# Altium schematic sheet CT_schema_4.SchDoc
size 517 x 390 mm
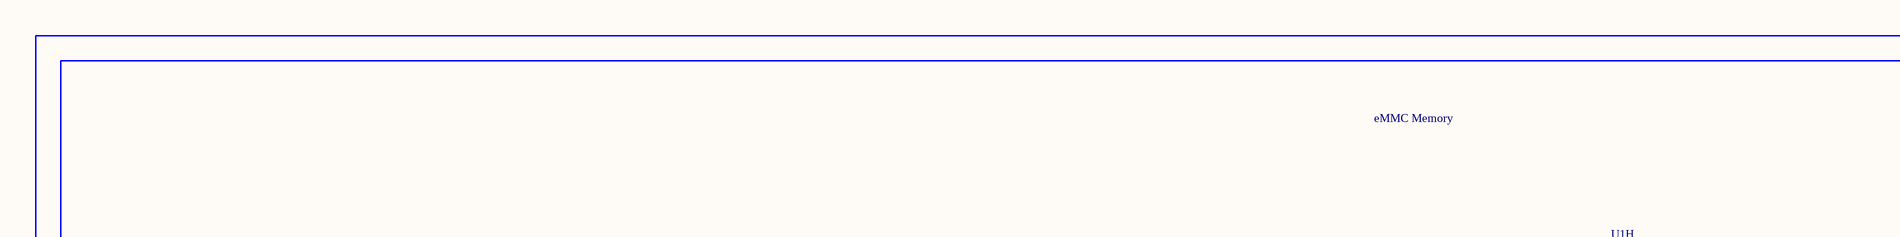
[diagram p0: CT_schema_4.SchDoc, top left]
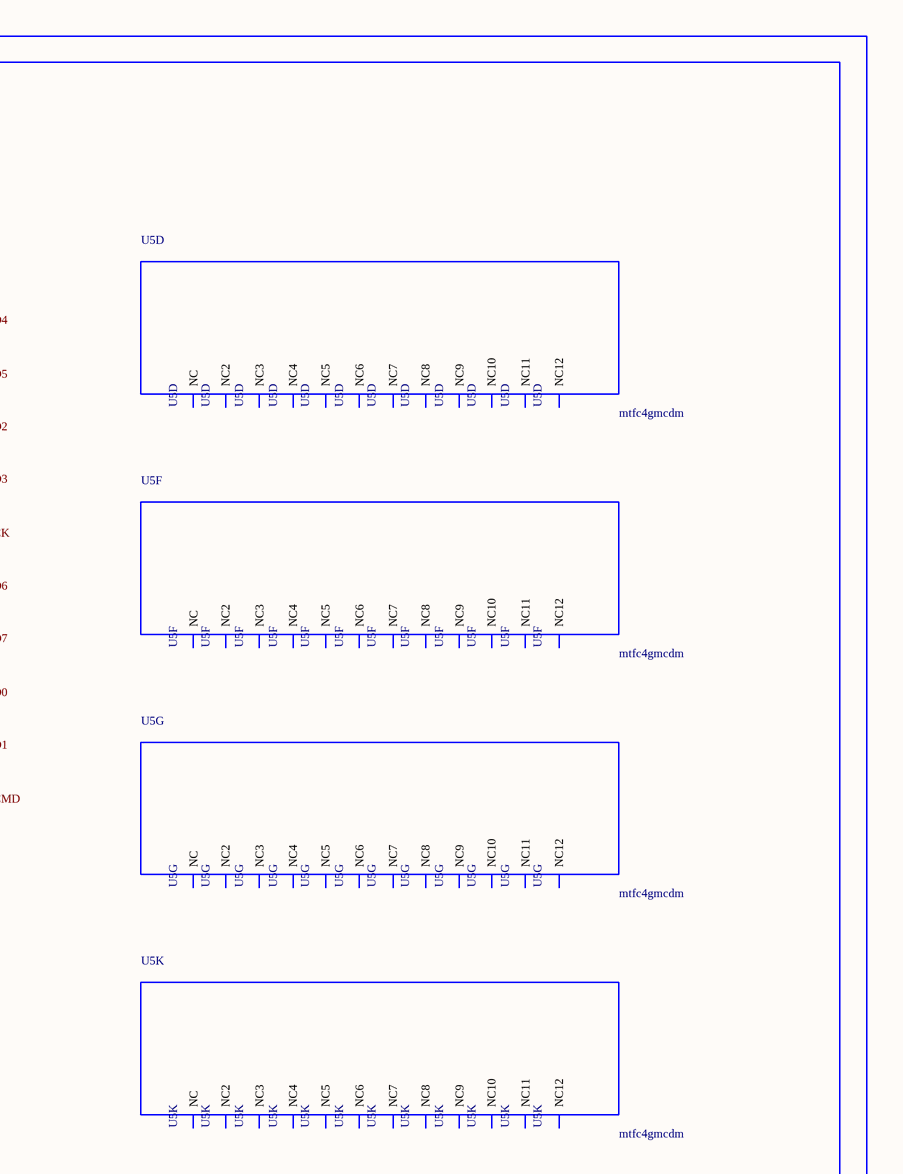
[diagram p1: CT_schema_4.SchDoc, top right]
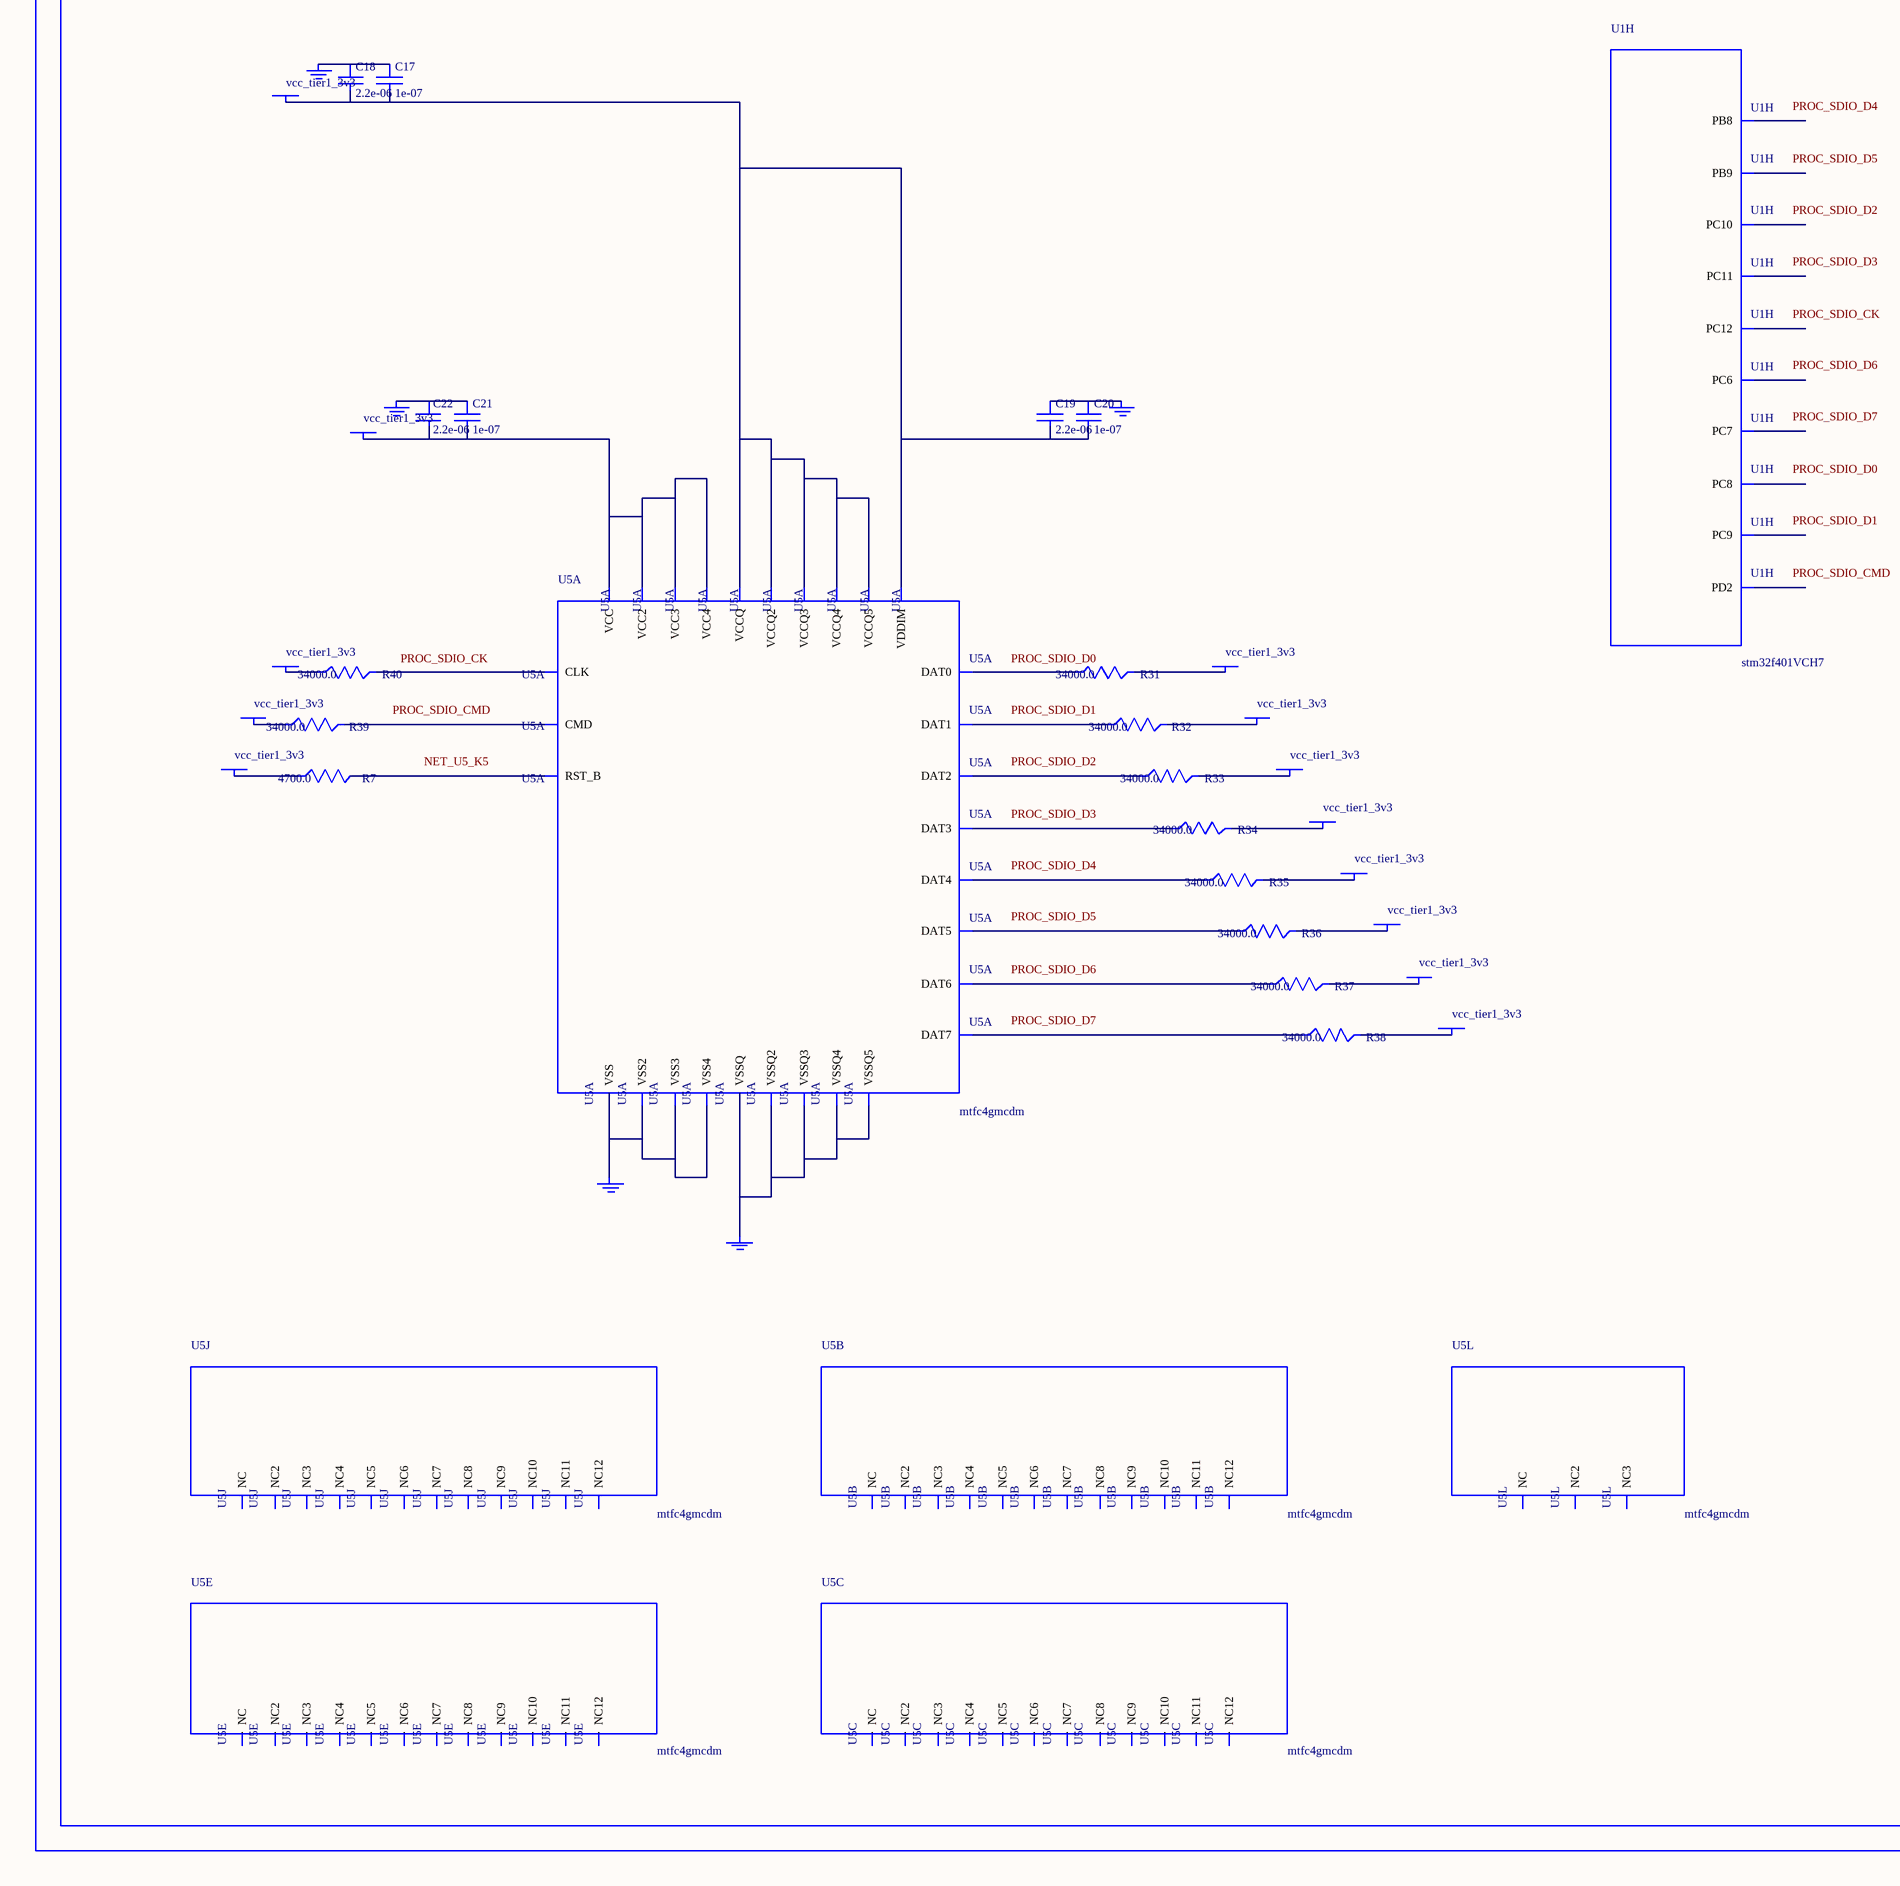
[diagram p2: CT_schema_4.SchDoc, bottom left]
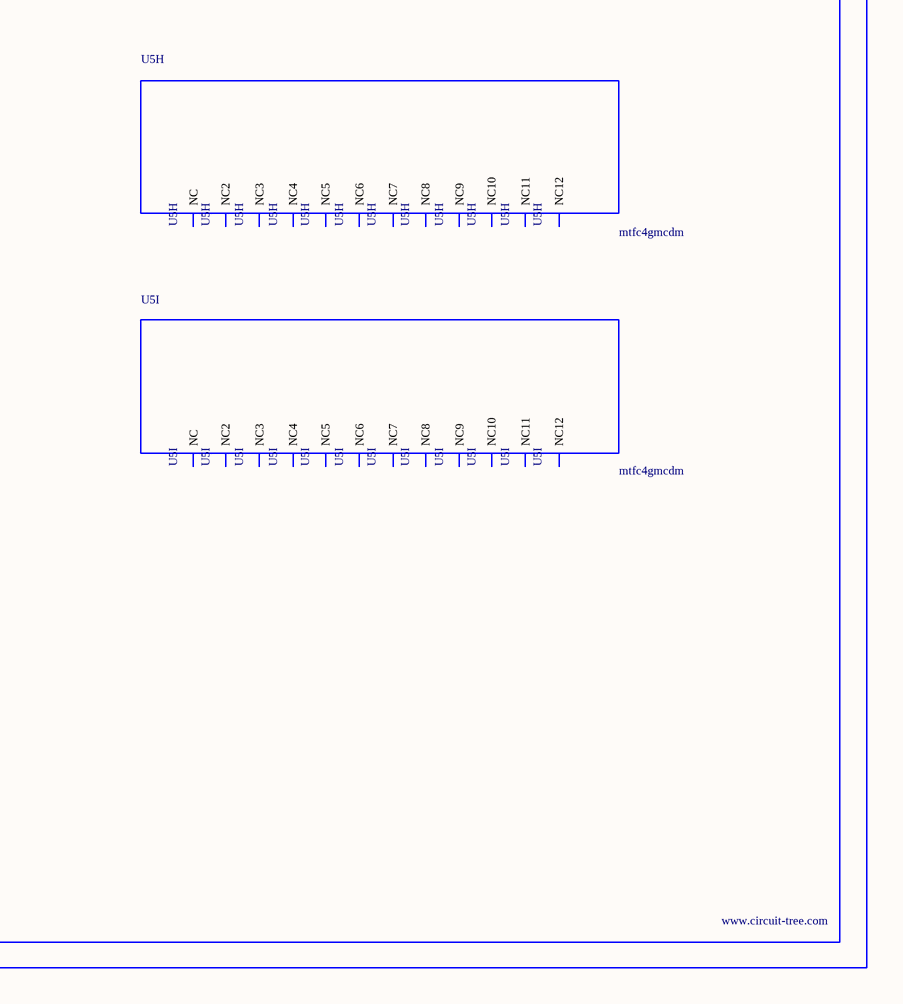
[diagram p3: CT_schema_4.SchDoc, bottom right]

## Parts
BORDER3  (no value)
C17  1e-07  [C0402]
C18  2.2e-06  [C0603]
C19  2.2e-06  [C0603]
C20  1e-07  [C0402]
C21  1e-07  [C0402]
C22  2.2e-06  [C0603]
GND_INSTANCE_3_0  (no value)
GND_INSTANCE_3_1  (no value)
GND_INSTANCE_3_2  (no value)
GND_INSTANCE_3_3  (no value)
GND_INSTANCE_3_4  (no value)
POWER_INSTANCE_3_0  vcc_tier1_3v3
POWER_INSTANCE_3_1  vcc_tier1_3v3
POWER_INSTANCE_3_2  vcc_tier1_3v3
POWER_INSTANCE_3_3  vcc_tier1_3v3
POWER_INSTANCE_3_4  vcc_tier1_3v3
POWER_INSTANCE_3_5  vcc_tier1_3v3
POWER_INSTANCE_3_6  vcc_tier1_3v3
POWER_INSTANCE_3_7  vcc_tier1_3v3
POWER_INSTANCE_3_8  vcc_tier1_3v3
POWER_INSTANCE_3_9  vcc_tier1_3v3
POWER_INSTANCE_3_10  vcc_tier1_3v3
POWER_INSTANCE_3_11  vcc_tier1_3v3
POWER_INSTANCE_3_12  vcc_tier1_3v3
R7  4700.0  [R0603]
R31  34000.0  [R0603]
R32  34000.0  [R0603]
R33  34000.0  [R0603]
R34  34000.0  [R0603]
R35  34000.0  [R0603]
R36  34000.0  [R0603]
R37  34000.0  [R0603]
R38  34000.0  [R0603]
R39  34000.0  [R0603]
R40  34000.0  [R0603]
U1  stm32f401VCH7  [UFBGA100]  (part H of 10)
U5  mtfc4gmcdm  [TFBGA-153]  (parts A,B,C,D,E,F,G,H,I,J,K,L of 12)

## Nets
NetC17_1: C17.1 C18.1 GND_INSTANCE_3_0.0(GND)
NetC17_2: C17.2 C18.2 C19.2 C20.2 POWER_INSTANCE_3_0.0(PWR) U5.C2(VDDIM) U5.C6(VCCQ) U5.M4(VCCQ2) U5.N4(VCCQ3) U5.P3(VCCQ4) U5.P5(VCCQ5)
NetC19_1: C19.1 C20.1 GND_INSTANCE_3_1.0(GND)
NetC21_1: C21.1 C22.1 GND_INSTANCE_3_2.0(GND)
NetC21_2: C21.2 C22.2 POWER_INSTANCE_3_1.0(PWR) U5.E6(VCC) U5.F5(VCC2) U5.J10(VCC3) U5.K9(VCC4)
NetGND_INSTANCE_3_3_0: GND_INSTANCE_3_3.0(GND) U5.E7(VSS) U5.G5(VSS2) U5.H10(VSS3) U5.K8(VSS4)
NetGND_INSTANCE_3_4_0: GND_INSTANCE_3_4.0(GND) U5.C4(VSSQ) U5.N2(VSSQ2) U5.N5(VSSQ3) U5.P4(VSSQ4) U5.P6(VSSQ5)
NetPOWER_INSTANCE_3_2_0: POWER_INSTANCE_3_2.0(PWR) R31.2
NetPOWER_INSTANCE_3_3_0: POWER_INSTANCE_3_3.0(PWR) R32.2
NetPOWER_INSTANCE_3_4_0: POWER_INSTANCE_3_4.0(PWR) R33.2
NetPOWER_INSTANCE_3_5_0: POWER_INSTANCE_3_5.0(PWR) R34.2
NetPOWER_INSTANCE_3_6_0: POWER_INSTANCE_3_6.0(PWR) R35.2
NetPOWER_INSTANCE_3_7_0: POWER_INSTANCE_3_7.0(PWR) R36.2
NetPOWER_INSTANCE_3_8_0: POWER_INSTANCE_3_8.0(PWR) R37.2
NetPOWER_INSTANCE_3_9_0: POWER_INSTANCE_3_9.0(PWR) R38.2
NetPOWER_INSTANCE_3_10_0: POWER_INSTANCE_3_10.0(PWR) R39.1
NetPOWER_INSTANCE_3_11_0: POWER_INSTANCE_3_11.0(PWR) R40.1
NetPOWER_INSTANCE_3_12_0: POWER_INSTANCE_3_12.0(PWR) R7.1
NetR7_2: R7.2 U5.K5(RST_B)
NetR31_1: R31.1 U5.A3(DAT0)
NetR32_1: R32.1 U5.A4(DAT1)
NetR33_1: R33.1 U5.A5(DAT2)
NetR34_1: R34.1 U5.B2(DAT3)
NetR35_1: R35.1 U5.B3(DAT4)
NetR36_1: R36.1 U5.B4(DAT5)
NetR37_1: R37.1 U5.B5(DAT6)
NetR38_1: R38.1 U5.B6(DAT7)
NetR39_2: R39.2 U5.M5(CMD)
NetR40_2: R40.2 U5.M6(CLK)

Not connected (* = marked no-connect by the designer): U1 A3(PB8) B3(PB9) B10(PC12) B11(PC10) C8(PD2) C10(PC11) D12(PC9) E10(PC8) E11(PC7) E12(PC6); U5 A1(NC) A2(NC7) A6(NC8) A7(NC9) A8(NC10) A9(NC11) A10(NC2) A11(NC3) A12(NC4) A13(NC5) A14(NC6) B1(NC12) B7(NC6) B8(NC7) B9(NC8) B10(NC) B11(NC2) B12(NC3) B13(NC4) B14(NC5) C1(NC9) C3(NC10) C5(NC11) C7(NC12) C8(NC6) C9(NC7) C10(NC) C11(NC2) C12(NC3) C13(NC4) C14(NC5) D1(NC8) D2(NC10) D3(NC11) D4(NC12) D12(NC9) D13(NC) D14(NC2) E1(NC3) E2(NC8) E3(NC9) E5(NC10) E8(NC11) E9(NC12) E10(NC4) E12(NC5) E13(NC6) E14(NC7) F1(NC) F2(NC6) F3(NC7) F10(NC2) F12(NC3) F13(NC4) F14(NC5) G1(NC8) G2(NC11) G3(NC12) G10(NC9) G12(NC10) G13(NC) G14(NC2) H1(NC3) H2(NC7) H3(NC8) H5(NC9) H12(NC4) H13(NC5) H14(NC6) J1(NC10) J2(NC11) J3(NC12) J5(NC4) J12(NC) J13(NC2) J14(NC3) K1(NC5) K2(NC9) K3(NC10) K6(NC11) K7(NC12) K10(NC6) K12(NC7) K13(NC8) K14(NC) L1(NC2) L2(NC6) L3(NC7) L12(NC3) L13(NC4) L14(NC5) M1(NC8) M2(NC9) M3(NC10) M7(NC11) M8(NC12) M9(NC6) M10(NC) M11(NC2) M12(NC3) M13(NC4) M14(NC5) N1(NC7) N3(NC8) N6(NC9) N7(NC10) N8(NC11) N9(NC12) N10(NC) N11(NC2) N12(NC3) N13(NC4) N14(NC5) P1(NC6) P2(NC9) P7(NC10) P8(NC11) P9(NC12) P10(NC7) P11(NC8) P12(NC) P13(NC2) P14(NC3)

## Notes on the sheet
- Labels drawn without touching a wire or pin: NET_U5_K5, PROC_SDIO_CK, PROC_SDIO_CMD, PROC_SDIO_D0, PROC_SDIO_D1, PROC_SDIO_D2, PROC_SDIO_D3, PROC_SDIO_D4, PROC_SDIO_D5, PROC_SDIO_D6, PROC_SDIO_D7

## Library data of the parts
BORDER3 = BORDER_PAGE3
C17 C20 C21 = C0402C104K3RACTU
C18 C19 C22 = C0603C225K8RACTU
GND_INSTANCE_3_0-GND_INSTANCE_3_4 = GND
POWER_INSTANCE_3_0-POWER_INSTANCE_3_12 = PWR
R7 = RC0603JR-074K7L
R31-R40 = ERA3ARB3402V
